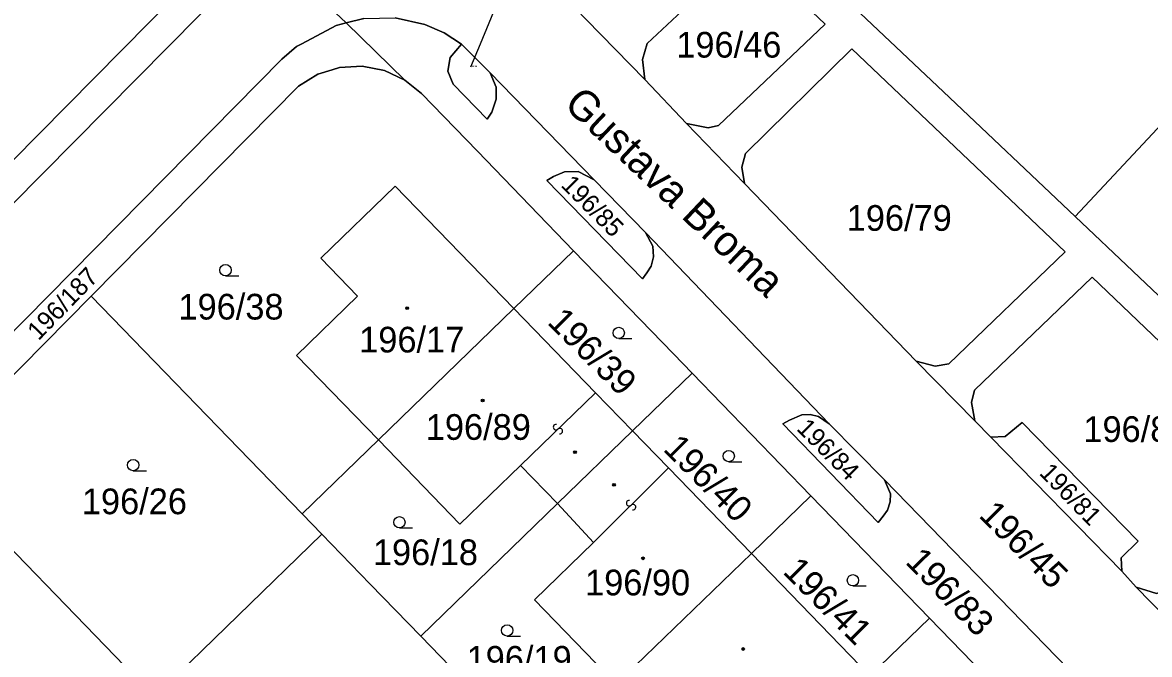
# Model space of a CAD drawing. Extents: x -598233 to -596890, y -1157848 to -1156431.
# Drawn here: x -597785.8 to -597711.3, y -1156652 to -1156610.2 of the extents above; entities that cross this region are included whole.
import ezdxf

# ---------------------------------------------------------------- set-up
doc = ezdxf.new("R2010")
doc.units = 0
for name, color, linetype in [('Level 1', 7, 'Continuous'), ('Level 11', 7, 'Continuous'), ('Level 13', 7, 'Continuous'), ('Level 3', 7, 'Continuous'), ('Level 4', 7, 'Continuous'), ('Level 5', 7, 'Continuous'), ('Level 57', 7, 'Continuous'), ('Level 60', 7, 'Continuous')]:
    doc.layers.add(name, color=color, linetype=linetype)

msp = doc.modelspace()

# ---------------------------------------------------------------- linework, layer by layer
at = {"layer": 'Level 1'}
for points in [[(-597770.04, -1156604.91), (-597770.43, -1156605.67), (-597771.37, -1156606.9), (-597772.06, -1156607.55), (-597809.37, -1156645.27), (-597844.57, -1156680.89), (-597887.68, -1156724.57), (-597890.67, -1156727.59), (-597892.67, -1156729.82), (-597894.6, -1156732.13), (-597895.83, -1156733.68), (-597898.85, -1156738.18), (-597899.77, -1156739.82), (-597900.7, -1156741.6), (-597901.53, -1156743.4), (-597902.31, -1156745.25), (-597903.05, -1156747.1), (-597903.7, -1156748.98), (-597904.57, -1156752.01), (-597905.43, -1156755.91), (-597911.89, -1156796.46), (-597912.06, -1156797.44), (-597912.32, -1156798.35)], [(-597770.04, -1156604.91), (-597764.42, -1156610.19)], [(-597741.92, -1156616.83), (-597740.48, -1156617.13), (-597739.8, -1156616.98), (-597732.73, -1156610.27), (-597737.89, -1156605.35), (-597744.51, -1156611.55), (-597744.82, -1156612.61), (-597744.68, -1156613.93)], [(-597731.99, -1156608.04), (-597724.9, -1156614.75), (-597716.2, -1156622.99)], [(-597775.61, -1156608.27), (-597790.21, -1156623.04)], [(-597799.56, -1156643.87), (-597768.68, -1156612.58), (-597767.71, -1156611.75), (-597767.37, -1156611.56), (-597765.09, -1156610.36), (-597764.42, -1156610.19)], [(-597764.42, -1156610.19), (-597763.26, -1156609.9), (-597761.19, -1156609.85), (-597759.22, -1156610.29), (-597757.94, -1156610.85), (-597756.8, -1156611.6)], [(-597764.42, -1156610.19), (-597760.55, -1156613.97)], [(-597744.68, -1156613.93), (-597748.56, -1156609.96)], [(-597716.2, -1156622.99), (-597704.06, -1156610)], [(-597754.91, -1156613.49), (-597754.51, -1156614.43), (-597754.5, -1156615.22), (-597754.79, -1156616.09), (-597755.1, -1156616.55), (-597757.35, -1156614.24), (-597757.7, -1156613.37), (-597757.54, -1156612.47), (-597756.8, -1156611.6)], [(-597756.8, -1156611.6), (-597754.91, -1156613.49)], [(-597726.72, -1156632.56), (-597725.46, -1156632.9), (-597724.56, -1156632.73), (-597716.86, -1156625.34), (-597730.98, -1156611.9), (-597738.01, -1156618.83), (-597738.25, -1156619.73), (-597738.08, -1156620.82)], [(-597781.3, -1156628.26), (-597767.58, -1156614.37), (-597766.3, -1156613.58), (-597765.36, -1156613.28), (-597764.87, -1156613.13), (-597763.38, -1156613.05), (-597761.9, -1156613.33), (-597760.55, -1156613.97)], [(-597749.38, -1156625.26), (-597755.75, -1156618.68), (-597759.45, -1156614.86), (-597760.55, -1156613.97)], [(-597754.91, -1156613.49), (-597748.03, -1156620.57)], [(-597744.68, -1156613.93), (-597741.92, -1156616.83)], [(-597738.08, -1156620.82), (-597741.92, -1156616.83)], [(-597748.03, -1156620.57), (-597749.08, -1156620.02), (-597749.98, -1156620.04), (-597750.72, -1156620.35), (-597751.16, -1156620.61), (-597744.82, -1156627.12), (-597744.54, -1156626.73), (-597744.26, -1156626.28), (-597744.09, -1156625.66), (-597744.13, -1156624.96), (-597744.62, -1156624.05)], [(-597744.62, -1156624.05), (-597748.03, -1156620.57)], [(-597738.08, -1156620.82), (-597726.72, -1156632.56)], [(-597753.33, -1156629.08), (-597761.18, -1156620.98), (-597766.1, -1156625.76), (-597763.67, -1156628.26), (-597767.72, -1156632.18), (-597762.3, -1156637.76)], [(-597700.93, -1156637.45), (-597716.2, -1156622.99)], [(-597744.62, -1156624.05), (-597732.48, -1156636.72)], [(-597749.38, -1156625.26), (-597753.33, -1156629.08)], [(-597749.38, -1156625.26), (-597742.78, -1156632.07), (-597741.53, -1156633.36)], [(-597712.16, -1156647.52), (-597710.81, -1156647.93), (-597710.09, -1156647.7), (-597701.55, -1156639.92), (-597715.07, -1156627.01), (-597722.85, -1156634.48), (-597723.06, -1156635.3), (-597722.83, -1156636.51)], [(-597792.16, -1156639.25), (-597781.3, -1156628.26)], [(-597781.3, -1156628.26), (-597767.35, -1156642.66)], [(-597762.3, -1156637.76), (-597753.33, -1156629.08)], [(-597753.33, -1156629.08), (-597747.93, -1156634.66)], [(-597722.83, -1156636.51), (-597726.72, -1156632.56)], [(-597745.48, -1156637.18), (-597741.53, -1156633.36)], [(-597733.68, -1156641.47), (-597741.53, -1156633.36)], [(-597747.93, -1156634.66), (-597745.48, -1156637.18)], [(-597732.48, -1156636.72), (-597733.17, -1156636.23), (-597733.73, -1156636.09), (-597734.29, -1156636.12), (-597735.1, -1156636.47), (-597735.53, -1156636.71), (-597729.24, -1156643.24), (-597728.9, -1156642.83), (-597728.61, -1156642.43), (-597728.43, -1156641.87), (-597728.42, -1156641.35), (-597728.82, -1156640.42)], [(-597722.83, -1156636.51), (-597721.77, -1156637.59)], [(-597745.48, -1156637.18), (-597750.44, -1156641.98)], [(-597745.48, -1156637.18), (-597743.11, -1156639.62)], [(-597728.82, -1156640.42), (-597732.48, -1156636.72)], [(-597721.77, -1156637.59), (-597720.83, -1156637.54), (-597719.71, -1156636.63), (-597712.04, -1156644.47), (-597713.16, -1156645.57), (-597713.12, -1156646.46)], [(-597767.35, -1156642.66), (-597762.3, -1156637.76)], [(-597752.9, -1156639.47), (-597756.91, -1156643.35), (-597762.3, -1156637.76)], [(-597713.12, -1156646.46), (-597721.77, -1156637.59)], [(-597792.16, -1156639.25), (-597777.12, -1156654.77)], [(-597752.9, -1156639.47), (-597750.44, -1156641.98)], [(-597743.11, -1156639.62), (-597737.62, -1156645.29)], [(-597728.82, -1156640.42), (-597716.67, -1156652.92)], [(-597737.62, -1156645.29), (-597733.68, -1156641.47)], [(-597725.84, -1156649.57), (-597733.68, -1156641.47)], [(-597750.44, -1156641.98), (-597759.5, -1156650.76)], [(-597750.44, -1156641.98), (-597748.06, -1156644.56)], [(-597766.03, -1156644.02), (-597767.35, -1156642.66)], [(-597777.12, -1156654.77), (-597766.03, -1156644.02)], [(-597766.03, -1156644.02), (-597762.84, -1156647.32), (-597759.5, -1156650.76)], [(-597748.06, -1156644.56), (-597751.96, -1156648.36), (-597746.56, -1156653.94)], [(-597746.56, -1156653.94), (-597737.62, -1156645.29)], [(-597729.78, -1156653.38), (-597737.62, -1156645.29)], [(-597713.12, -1156646.46), (-597712.16, -1156647.52)], [(-597708.25, -1156651.53), (-597712.16, -1156647.52)], [(-597729.78, -1156653.38), (-597725.84, -1156649.57)], [(-597725.84, -1156649.57), (-597717.99, -1156657.66)], [(-597756.27, -1156654.1), (-597759.5, -1156650.76)]]:
    msp.add_lwpolyline(points, dxfattribs=at)
at = {"layer": 'Level 13'}
for centre, start, end in [((-597750.547, -1156636.926), 81.43546, 313.53346), ((-597750.293, -1156637.193), 261.22101, 133.81101), ((-597745.709, -1156641.958), 82.3148, 314.4128), ((-597745.451, -1156642.221), 262.10034, 134.69034)]:
    msp.add_arc(centre, 0.184, start, end, dxfattribs=at)
at = {"layer": 'Level 3'}
for points in [[(-597752.9, -1156639.47), (-597747.93, -1156634.66)], [(-597748.06, -1156644.56), (-597743.11, -1156639.62)]]:
    msp.add_lwpolyline(points, dxfattribs=at)
at = {"layer": 'Level 5'}
for p, q in [((-597772.41, -1156626.92), (-597771.535, -1156626.92)), ((-597746.4, -1156631.07), (-597745.525, -1156631.07)), ((-597739.12, -1156639.22), (-597738.245, -1156639.22)), ((-597778.52, -1156639.81), (-597777.645, -1156639.81)), ((-597760.91, -1156643.6), (-597760.035, -1156643.6)), ((-597730.9, -1156647.44), (-597730.025, -1156647.44)), ((-597753.78, -1156650.75), (-597752.905, -1156650.75))]:
    msp.add_line(p, q, dxfattribs=at)
for centre, radius in [((-597772.41, -1156626.545), 0.375), ((-597760.39, -1156629.05), 0.09), ((-597760.39, -1156629.05), 0.0521), ((-597746.4, -1156630.695), 0.375), ((-597755.4, -1156635.17), 0.09), ((-597755.4, -1156635.17), 0.0521), ((-597749.29, -1156638.58), 0.09), ((-597749.29, -1156638.58), 0.0521), ((-597739.12, -1156638.845), 0.375), ((-597778.52, -1156639.435), 0.375), ((-597746.71, -1156640.75), 0.09), ((-597746.71, -1156640.75), 0.0521), ((-597760.91, -1156643.225), 0.375), ((-597744.79, -1156645.61), 0.09), ((-597744.79, -1156645.61), 0.0521), ((-597730.9, -1156647.065), 0.375), ((-597753.78, -1156650.375), 0.375), ((-597738.16, -1156651.61), 0.09), ((-597738.16, -1156651.61), 0.0521)]:
    msp.add_circle(centre, radius, dxfattribs=at)
at = {"layer": 'Level 57'}
for p, q in [((-597755.549, -1156611.564), (-597754.394, -1156608.795)), ((-597756.19, -1156613.1), (-597755.549, -1156611.564))]:
    msp.add_line(p, q, dxfattribs=at)
at = {"layer": 'Level 60'}
for points in [[(-597790.21, -1156623.04), (-597813.05, -1156601.37), (-597799.34, -1156587.09), (-597775.61, -1156608.27)], [(-597704.06, -1156610), (-597716.2, -1156622.99), (-597724.9, -1156614.75), (-597731.99, -1156608.04), (-597719.85, -1156595.06), (-597712.34, -1156602.16), (-597713.51, -1156603.33), (-597711.26, -1156605.57), (-597710.04, -1156604.34)], [(-597740.48, -1156617.13), (-597741.92, -1156616.83), (-597744.68, -1156613.93), (-597744.82, -1156612.61), (-597744.51, -1156611.55), (-597737.89, -1156605.35), (-597732.73, -1156610.27), (-597739.8, -1156616.98)], [(-597801.33, -1156648.55), (-597801.25, -1156647.52), (-597801, -1156646.53), (-597800.69, -1156645.56), (-597800.21, -1156644.66), (-597799.56, -1156643.87), (-597768.68, -1156612.58), (-597767.71, -1156611.75), (-597767.37, -1156611.56), (-597765.09, -1156610.36), (-597764.42, -1156610.19), (-597760.55, -1156613.97), (-597761.9, -1156613.33), (-597763.38, -1156613.05), (-597764.87, -1156613.13), (-597765.36, -1156613.28), (-597766.3, -1156613.58), (-597767.58, -1156614.37), (-597781.3, -1156628.26), (-597792.16, -1156639.25), (-597797.86, -1156645.02)], [(-597716.2, -1156622.99), (-597704.06, -1156610), (-597688.79, -1156624.46), (-597700.93, -1156637.45)], [(-597756.8, -1156611.6), (-597754.91, -1156613.49), (-597754.51, -1156614.43), (-597754.5, -1156615.22), (-597754.79, -1156616.09), (-597755.1, -1156616.55), (-597757.35, -1156614.24), (-597757.7, -1156613.37), (-597757.54, -1156612.47)], [(-597725.46, -1156632.9), (-597726.72, -1156632.56), (-597738.08, -1156620.82), (-597738.25, -1156619.73), (-597738.01, -1156618.83), (-597730.98, -1156611.9), (-597716.86, -1156625.34), (-597724.56, -1156632.73)], [(-597749.38, -1156625.26), (-597753.33, -1156629.08), (-597761.18, -1156620.98), (-597766.1, -1156625.76), (-597763.67, -1156628.26), (-597767.72, -1156632.18), (-597762.3, -1156637.76), (-597767.35, -1156642.66), (-597781.3, -1156628.26), (-597767.58, -1156614.37), (-597766.3, -1156613.58), (-597765.36, -1156613.28), (-597764.87, -1156613.13), (-597763.38, -1156613.05), (-597761.9, -1156613.33), (-597760.55, -1156613.97), (-597759.45, -1156614.86), (-597755.75, -1156618.68)], [(-597749.08, -1156620.02), (-597748.03, -1156620.57), (-597744.62, -1156624.05), (-597744.13, -1156624.96), (-597744.09, -1156625.66), (-597744.26, -1156626.28), (-597744.54, -1156626.73), (-597744.82, -1156627.12), (-597751.16, -1156620.61), (-597750.72, -1156620.35), (-597749.98, -1156620.04)], [(-597753.33, -1156629.08), (-597762.3, -1156637.76), (-597767.72, -1156632.18), (-597763.67, -1156628.26), (-597766.1, -1156625.76), (-597761.18, -1156620.98)], [(-597753.33, -1156629.08), (-597749.38, -1156625.26), (-597742.78, -1156632.07), (-597741.53, -1156633.36), (-597745.48, -1156637.18), (-597747.93, -1156634.66)], [(-597710.81, -1156647.93), (-597712.16, -1156647.52), (-597713.12, -1156646.46), (-597713.16, -1156645.57), (-597712.04, -1156644.47), (-597719.71, -1156636.63), (-597720.83, -1156637.54), (-597721.77, -1156637.59), (-597722.83, -1156636.51), (-597723.06, -1156635.3), (-597722.85, -1156634.48), (-597715.07, -1156627.01), (-597701.55, -1156639.92), (-597710.09, -1156647.7)], [(-597777.12, -1156654.77), (-597792.16, -1156639.25), (-597781.3, -1156628.26), (-597767.35, -1156642.66), (-597766.03, -1156644.02)], [(-597752.9, -1156639.47), (-597756.91, -1156643.35), (-597762.3, -1156637.76), (-597753.33, -1156629.08), (-597747.93, -1156634.66), (-597745.48, -1156637.18), (-597750.44, -1156641.98)], [(-597745.48, -1156637.18), (-597741.53, -1156633.36), (-597733.68, -1156641.47), (-597737.62, -1156645.29), (-597743.11, -1156639.62)], [(-597733.17, -1156636.23), (-597732.48, -1156636.72), (-597728.82, -1156640.42), (-597728.42, -1156641.35), (-597728.43, -1156641.87), (-597728.61, -1156642.43), (-597728.9, -1156642.83), (-597729.24, -1156643.24), (-597735.53, -1156636.71), (-597735.1, -1156636.47), (-597734.29, -1156636.12), (-597733.73, -1156636.09)], [(-597748.06, -1156644.56), (-597750.44, -1156641.98), (-597745.48, -1156637.18), (-597743.11, -1156639.62), (-597737.62, -1156645.29), (-597746.56, -1156653.94), (-597751.96, -1156648.36)], [(-597721.77, -1156637.59), (-597720.83, -1156637.54), (-597719.71, -1156636.63), (-597712.04, -1156644.47), (-597713.16, -1156645.57), (-597713.12, -1156646.46)], [(-597756.91, -1156643.35), (-597752.9, -1156639.47), (-597750.44, -1156641.98), (-597759.5, -1156650.76), (-597762.84, -1156647.32), (-597766.03, -1156644.02), (-597767.35, -1156642.66), (-597762.3, -1156637.76)], [(-597792.16, -1156639.25), (-597777.12, -1156654.77), (-597786.06, -1156663.43), (-597799.05, -1156650.1), (-597799.3, -1156648.62), (-597799.1, -1156647.13), (-597798.47, -1156645.77), (-597797.86, -1156645.02)], [(-597737.62, -1156645.29), (-597733.68, -1156641.47), (-597725.84, -1156649.57), (-597729.78, -1156653.38)], [(-597759.5, -1156650.76), (-597750.44, -1156641.98), (-597748.06, -1156644.56), (-597751.96, -1156648.36), (-597746.56, -1156653.94), (-597751.65, -1156658.87), (-597756.27, -1156654.1)], [(-597777.12, -1156654.77), (-597766.03, -1156644.02), (-597762.84, -1156647.32), (-597759.5, -1156650.76), (-597756.27, -1156654.1), (-597776.31, -1156673.51), (-597780.75, -1156668.92), (-597785.95, -1156663.55), (-597786.06, -1156663.43)], [(-597737.62, -1156645.29), (-597729.78, -1156653.38), (-597734.79, -1156658.23), (-597737.09, -1156655.81), (-597737.21, -1156655.93), (-597737.3, -1156655.85), (-597741.13, -1156659.57), (-597746.56, -1156653.94)], [(-597717.99, -1156657.66), (-597721.93, -1156661.48), (-597729.78, -1156653.38), (-597725.84, -1156649.57)]]:
    msp.add_lwpolyline(points, close=True, dxfattribs=at)
for points in [[(-597753.87, -1156590.06), (-597752.57, -1156588.64), (-597749.61, -1156591.41), (-597753.89, -1156595.98), (-597754.96, -1156597.37), (-597755.48, -1156598.68), (-597755.68, -1156600.09), (-597755.53, -1156601.55), (-597754.98, -1156603.02), (-597754.26, -1156604.09), (-597751.83, -1156606.55), (-597748.56, -1156609.96), (-597744.68, -1156613.93), (-597741.92, -1156616.83), (-597738.08, -1156620.82), (-597726.72, -1156632.56), (-597722.83, -1156636.51), (-597721.77, -1156637.59), (-597713.12, -1156646.46), (-597712.16, -1156647.52), (-597708.25, -1156651.53)], [(-597866.78, -1156700.56), (-597865.27, -1156699.03), (-597864.24, -1156697.99), (-597856.92, -1156690.58), (-597851.3, -1156684.89), (-597845.68, -1156679.19), (-597836.72, -1156670.13), (-597804.95, -1156637.96), (-597790.21, -1156623.04), (-597775.61, -1156608.27), (-597773.83, -1156606.36), (-597773.26, -1156605.64), (-597773, -1156605.09), (-597772.82, -1156604.64), (-597772.85, -1156603.17), (-597773.27, -1156602.07), (-597774.4, -1156600.81), (-597770.04, -1156604.91), (-597770.43, -1156605.67), (-597771.37, -1156606.9), (-597772.06, -1156607.55), (-597809.37, -1156645.27), (-597844.57, -1156680.89), (-597887.68, -1156724.57)], [(-597887.68, -1156724.57), (-597844.57, -1156680.89), (-597809.37, -1156645.27), (-597772.06, -1156607.55), (-597771.37, -1156606.9), (-597770.43, -1156605.67), (-597770.04, -1156604.91), (-597764.42, -1156610.19), (-597765.09, -1156610.36), (-597767.37, -1156611.56), (-597767.71, -1156611.75), (-597768.68, -1156612.58), (-597799.56, -1156643.87), (-597811.76, -1156656.27), (-597840.45, -1156685.25), (-597882.81, -1156728.2)], [(-597763.26, -1156609.9), (-597764.42, -1156610.19), (-597770.04, -1156604.91)], [(-597701.55, -1156639.92), (-597715.07, -1156627.01), (-597722.85, -1156634.48), (-597723.06, -1156635.3), (-597722.83, -1156636.51), (-597726.72, -1156632.56), (-597725.46, -1156632.9), (-597724.56, -1156632.73), (-597716.86, -1156625.34), (-597730.98, -1156611.9), (-597738.01, -1156618.83), (-597738.25, -1156619.73), (-597738.08, -1156620.82), (-597741.92, -1156616.83), (-597740.48, -1156617.13), (-597739.8, -1156616.98), (-597732.73, -1156610.27), (-597737.89, -1156605.35), (-597744.51, -1156611.55), (-597744.82, -1156612.61), (-597744.68, -1156613.93), (-597748.56, -1156609.96)], [(-597731.99, -1156608.04), (-597724.9, -1156614.75), (-597716.2, -1156622.99), (-597700.93, -1156637.45)], [(-597710.15, -1156665.76), (-597713.34, -1156662.46), (-597717.99, -1156657.66), (-597725.84, -1156649.57), (-597733.68, -1156641.47), (-597741.53, -1156633.36), (-597742.78, -1156632.07), (-597749.38, -1156625.26), (-597755.75, -1156618.68), (-597759.45, -1156614.86), (-597760.55, -1156613.97), (-597764.42, -1156610.19), (-597763.26, -1156609.9)], [(-597701.06, -1156669.09), (-597713.26, -1156656.43), (-597716.67, -1156652.92), (-597728.82, -1156640.42), (-597732.48, -1156636.72), (-597744.62, -1156624.05), (-597748.03, -1156620.57), (-597754.91, -1156613.49), (-597756.8, -1156611.6), (-597757.94, -1156610.85), (-597759.22, -1156610.29), (-597761.19, -1156609.85)], [(-597761.19, -1156609.85), (-597759.22, -1156610.29), (-597757.94, -1156610.85), (-597756.8, -1156611.6), (-597757.54, -1156612.47), (-597757.7, -1156613.37), (-597757.35, -1156614.24), (-597755.1, -1156616.55), (-597754.79, -1156616.09), (-597754.5, -1156615.22), (-597754.51, -1156614.43), (-597754.91, -1156613.49), (-597748.03, -1156620.57), (-597749.08, -1156620.02), (-597749.98, -1156620.04), (-597750.72, -1156620.35), (-597751.16, -1156620.61), (-597744.82, -1156627.12), (-597744.54, -1156626.73), (-597744.26, -1156626.28), (-597744.09, -1156625.66), (-597744.13, -1156624.96), (-597744.62, -1156624.05), (-597732.48, -1156636.72), (-597733.17, -1156636.23), (-597733.73, -1156636.09), (-597734.29, -1156636.12), (-597735.1, -1156636.47), (-597735.53, -1156636.71), (-597729.24, -1156643.24), (-597728.9, -1156642.83), (-597728.61, -1156642.43), (-597728.43, -1156641.87), (-597728.42, -1156641.35), (-597728.82, -1156640.42), (-597716.67, -1156652.92)], [(-597708.25, -1156651.53), (-597712.16, -1156647.52), (-597710.81, -1156647.93)]]:
    msp.add_lwpolyline(points, dxfattribs=at)

# ---------------------------------------------------------------- texts
at = {"layer": 'Level 11'}
msp.add_text('Gustava Broma', height=2, rotation=316.61988, dxfattribs=at).set_placement((-597750.106, -1156615.681))
at = {"layer": 'Level 4'}
for s, p in [('196/46', (-597742.59, -1156612.48)), ('196/79', (-597731.315, -1156623.94)), ('196/38', (-597775.525, -1156629.81)), ('196/17', (-597763.568, -1156631.99)), ('196/89', (-597759.164, -1156637.77)), ('196/80', (-597715.658, -1156637.91)), ('196/26', (-597781.915, -1156642.69)), ('196/18', (-597762.661, -1156646.06)), ('196/90', (-597748.624, -1156648.06)), ('196/19', (-597756.463, -1156653.11))]:
    msp.add_text(s, height=1.7, dxfattribs=at).set_placement(p)
for s, height, rotation, p in [('196/86', 0.1, 0.1071, (-597756.19, -1156613.1)), ('196/85', 1.2, 315, (-597750.277, -1156620.973)), ('196/187', 1.2, 45.9, (-597784.78, -1156631.247)), ('196/39', 1.7, 315, (-597751.179, -1156630.051)), ('196/84', 1.2, 315, (-597734.686, -1156637.084)), ('196/40', 1.7, 315, (-597743.522, -1156638.438)), ('196/81', 1.2, 314.1, (-597718.628, -1156640.014)), ('196/45', 1.7, 315, (-597722.644, -1156642.826)), ('196/83', 1.7, 314.1, (-597727.498, -1156645.896)), ('196/41', 1.7, 315, (-597735.608, -1156646.552))]:
    msp.add_text(s, height=height, rotation=rotation, dxfattribs=at).set_placement(p)

doc.saveas('drawing.dxf')
